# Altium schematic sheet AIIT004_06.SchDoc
size A3
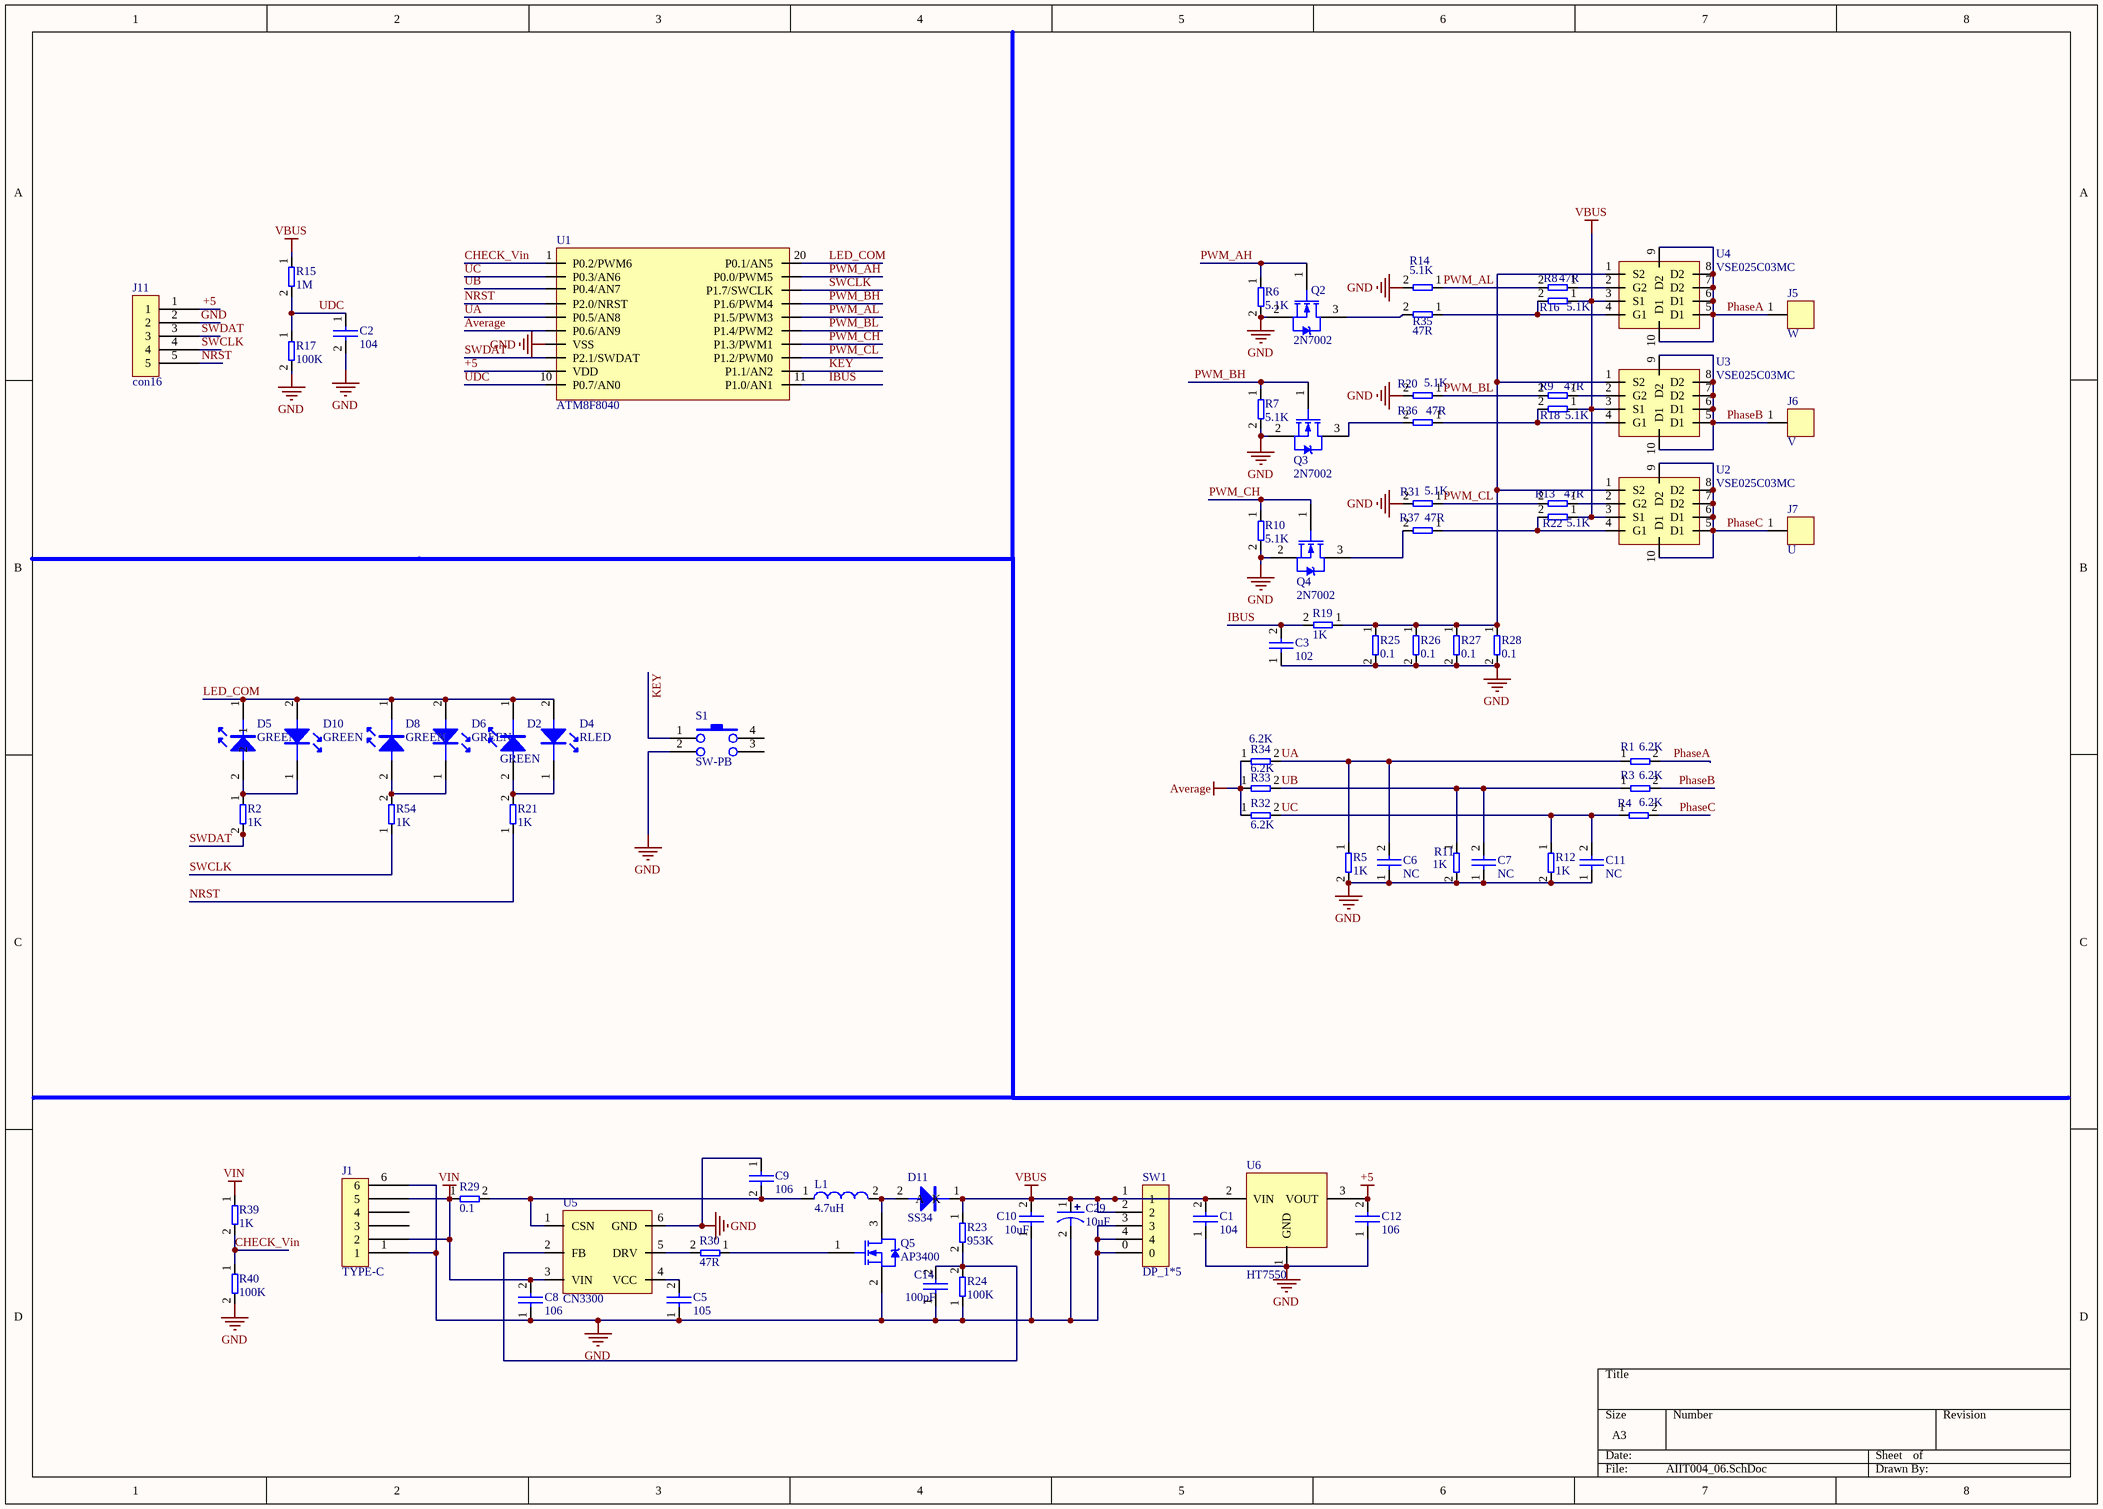
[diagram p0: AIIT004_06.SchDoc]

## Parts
C1  104  [0603M]
C2  104  [0402M]
C3  102  [0402M]
C5  105  [0402M]
C6  NC  [0402M]
C7  NC  [0402M]
C8  106  [0603M]
C9  106  [0603M]
C10  10uF  [0805MS]
C11  NC  [0402M]
C12  106  [0603M]
C14  100pF  [0402M]
C29  10uF  [0805MS]
D2  GREEN  [SMD_LED_0603]
D4  RLED  [SMD_LED_0603]
D5  GREEN  [SMD_LED_0603]
D6  GREEN  [SMD_LED_0603]
D8  GREEN  [SMD_LED_0603]
D10  GREEN  [SMD_LED_0603]
D11  SS34  [SMA]
J1  TYPE-C  [TYPE-C-CV]
J5  W  [TP1]
J6  V  [TP1]
J7  U  [TP1]
J11  con16  [SIP6-2.0]
L1  4.7uH  [L_CD58]
Q2  2N7002  [SOT-23]
Q3  2N7002  [SOT-23]
Q4  2N7002  [SOT-23]
Q5  AP3400  [SOT23L]
R1  6.2K  [0402M]
R2  1K  [0402M]
R3  6.2K  [0402M]
R4  6.2K  [0402M]
R5  1K  [0402M]
R6  5.1K  [0402M]
R7  5.1K  [0402M]
R8  47R  [0402M]
R9  47R  [0402M]
R10  5.1K  [0402M]
R11  1K  [0402M]
R12  1K  [0402M]
R13  47R  [0402M]
R14  5.1K  [0402M]
R15  1M  [0402M]
R16  5.1K  [0402M]
R17  100K  [0402M]
R18  5.1K  [0402M]
R19  1K  [0402M]
R20  5.1K  [0402M]
R21  1K  [0402M]
R22  5.1K  [0402M]
R23  953K  [0402M]
R24  100K  [0402M]
R25  0.1  [1206M]
R26  0.1  [1206M]
R27  0.1  [1206M]
R28  0.1  [1206M]
R29  0.1  [1206M]
R30  47R  [0402M]
R31  5.1K  [0402M]
R32  6.2K  [0402M]
R33  6.2K  [0402M]
R34  6.2K  [0402M]
R35  47R  [0402M]
R36  47R  [0402M]
R37  47R  [0402M]
R39  1K  [0402M]
R40  100K  [0402M]
R54  1K  [0402M]
S1  SW-PB  [6MM-BTNSMD]
SW1  DP_1*5  [CH1.25_4PVH]
U1  ATM8F8040  [SSOP20]
U2  VSE025C03MC  [DFN-8_3333]
U3  VSE025C03MC  [DFN-8_3333]
U4  VSE025C03MC  [DFN-8_3333]
U5  CN3300  [SOT23-6]
U6  HT7550  [SOT89]

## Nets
+5: C12.2 J11.1 U1.9(VDD) U6.3(VOUT)
Average: R32.1 R33.1 R34.1 U1.6(P0.6/AN9)
GND: C1.1 C2.2 C3.1 C5.1 C6.1 C7.1 C8.1 C9.1 C10.1 C11.1 C12.1 C14.1 C29.2 J1.1 J1.6 J11.2 Q2.2(S) Q3.2(S) Q4.2(S) Q5.2(S) R5.2 R6.2 R7.2 R10.2 R11.2 R12.2 R14.2 R17.2 R20.2 R24.1 R25.2 R26.2 R27.2 R28.2 R31.2 R40.2 S1.2 SW1.0 SW1.3 SW1.4 U1.7(VSS) U5.6(GND) U6.1(GND)
VBUS: C1.2 C10.2 C29.1 D11.1(K) R15.1 R16.1 R18.1 R22.1 R23.1 SW1.1 SW1.2 U2.3(S1) U3.3(S1) U4.3(S1) U6.2(VIN)
VIN: C8.2 J1.2 J1.5 R29.1 R39.1 U5.3(VIN)
CHECK_Vin: R39.2 R40.1 U1.1(P0.2/PWM6)
IBUS: C3.2 R19.2 U1.11(P1.0/AN1)
KEY: S1.1 U1.12(P1.1/AN2)
LED_COM: D2.1 D4.2 D5.1 D6.2 D8.1 D10.2 U1.20(P0.1/AN5)
NRST: J11.5 R21.1 U1.4(P2.0/NRST)
PhaseA: J5.1 R1.2 U4.5(D1) U4.6(D1) U4.7(D2) U4.8(D2) U4.9(D2) U4.10(D1)
PhaseB: J6.1 R3.2 U3.5(D1) U3.6(D1) U3.7(D2) U3.8(D2) U3.9(D2) U3.10(D1)
PhaseC: J7.1 R4.2 U2.5(D1) U2.6(D1) U2.7(D2) U2.8(D2) U2.9(D2) U2.10(D1)
PWM_AH: Q2.1(G) R6.1 U1.19(P0.0/PWM5)
PWM_AL: R8.2 R14.1 U1.16(P1.5/PWM3)
PWM_BH: Q3.1(G) R7.1 U1.17(P1.6/PWM4)
PWM_BL: R9.2 R20.1 U1.15(P1.4/PWM2)
PWM_CH: Q4.1(G) R10.1 U1.14(P1.3/PWM1)
PWM_CL: R13.2 R31.1 U1.13(P1.2/PWM0)
SWCLK: J11.4 R54.1 U1.18(P1.7/SWCLK)
SWDAT: J11.3 R2.2 U1.8(P2.1/SWDAT)
UA: C6.2 R1.1 R5.1 R34.2 U1.5(P0.5/AN8)
UB: C7.2 R3.1 R11.1 R33.2 U1.3(P0.4/AN7)
UC: C11.2 R4.1 R12.1 R32.2 U1.2(P0.3/AN6)
UDC: C2.1 R15.2 R17.1 U1.10(P0.7/AN0)
NetC5_2: C5.2 U5.4(VCC)
NetC9_2: C9.2 L1.1 R29.2 U5.1(CSN)
NetC14_2: C14.2 R23.2 R24.2 U5.2(FB)
NetD2_2: D2.2 D4.1 R21.2
NetD5_2: D5.2 D10.1 R2.1
NetD6_1: D6.1 D8.2 R54.2
NetD11_2: D11.2(A) L1.2 Q5.3(D)
NetQ2_3: Q2.3(D) R35.2
NetQ3_3: Q3.3(D) R36.2
NetQ4_3: Q4.3(D) R37.2
NetQ5_1: Q5.1(G) R30.1
NetR8_1: R8.1 U4.2(G2)
NetR9_1: R9.1 U3.2(G2)
NetR13_1: R13.1 U2.2(G2)
NetR16_2: R16.2 R35.1 U4.4(G1)
NetR18_2: R18.2 R36.1 U3.4(G1)
NetR19_1: R19.1 R25.1 R26.1 R27.1 R28.1 U2.1(S2) U3.1(S2) U4.1(S2)
NetR22_2: R22.2 R37.1 U2.4(G1)
NetR30_2: R30.2 U5.5(DRV)

Not connected (* = marked no-connect by the designer): J1 3 4; S1 3 4

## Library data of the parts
C1-C3 C5-C12 C14 = CAP
C29 = DIP_ECAP: 直插电解电容
D2 D4-D6 D8 D10 = LED
D11 = DIODE
J1 = 单排针2.54mm-6P
J5-J7 = testpoint
J11 = 单排针2.54mm-5P
L1 = Inductor: Code_IEC: 1005
Q2-Q5 = NMOS-2: N-Channel Power MOSFET; Note: Pin 2 is electrically connected to pin 4.
R1-R37 R39 R40 R54 = R
S1 = MT_KT_D_6*6: （贴片）按键
SW1 = DP_1*5: 单排5芯接插件
U2-U4 = KS4606
U6 = HT7550: 立创物料号：C59200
